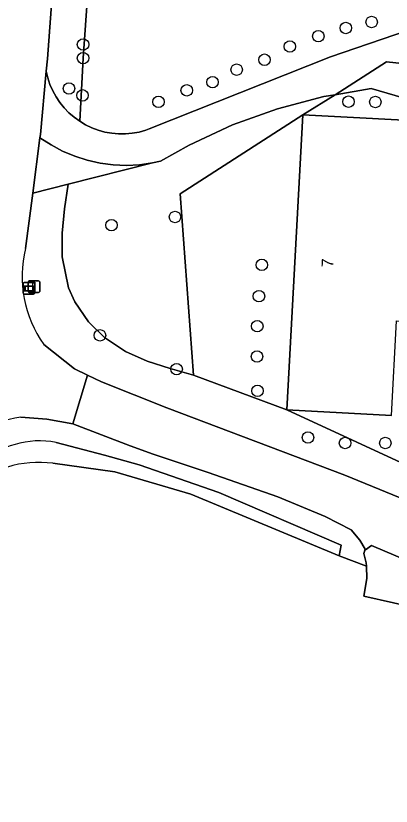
# Model space of a CAD drawing. Extents: x 163859 to 164644, y 379566 to 382155.
# Drawn here: x 164438.1 to 164470.1, y 381270.8 to 381338.2 of the extents above; entities that cross this region are included whole.
import ezdxf

# ---------------------------------------------------------------- set-up
doc = ezdxf.new("R2010")
doc.units = 0
for name, color, linetype in [('IMGEO_Boom', 7, 'Continuous'), ('IMGEO_Erf', 7, 'Continuous'), ('IMGEO_Grasland_overig', 7, 'Continuous'), ('IMGEO_Groenvoorziening', 7, 'Continuous'), ('IMGEO_Lichtmast', 7, 'Continuous'), ('IMGEO_Pand', 7, 'Continuous'), ('IMGEO_Pand_nummerreeks', 7, 'Continuous'), ('IMGEO_Rijbaan_lokaal_gesloten', 7, 'Continuous'), ('IMGEO_Rijbaan_lokaal_onverhard', 7, 'Continuous'), ('IMGEO_Rijbaan_lokaal_open', 7, 'Continuous'), ('IMGEO_Waterloop', 7, 'Continuous'), ('IMGEO_Wegwijzer', 7, 'Continuous')]:
    doc.layers.add(name, color=color, linetype=linetype)

msp = doc.modelspace()

# ---------------------------------------------------------------- linework, layer by layer
at = {"layer": 'IMGEO_Boom'}
for centre in [(164466.181, 381337.123), (164468.388, 381337.632), (164463.846, 381336.431), (164443.791, 381335.711), (164461.422, 381335.541), (164443.791, 381334.557), (164459.253, 381334.417), (164456.883, 381333.568), (164454.831, 381332.506), (164442.59, 381331.967), (164452.627, 381331.808), (164443.738, 381331.377), (164450.222, 381330.825), (164466.417, 381330.842), (164468.704, 381330.815), (164451.629, 381321.013), (164446.217, 381320.312), (164459.029, 381316.926), (164458.783, 381314.264), (164458.64, 381311.705), (164445.23, 381310.921), (164458.619, 381309.125), (164451.764, 381308.047), (164458.66, 381306.197), (164462.962, 381302.22), (164466.124, 381301.745), (164469.554, 381301.745)]:
    msp.add_circle(centre, 0.489, dxfattribs=at)
at = {"layer": 'IMGEO_Erf'}
for points in [[(164476.058, 381329.711), (164468.34, 381331.955), (164465.276, 381331.438), (164462.527, 381329.731), (164474.919, 381329.061)], [(164470.072, 381304.084), (164461.167, 381304.566), (164478.695, 381296.475)], [(164540.482, 381264.151), (164540.217, 381265.042), (164529.128, 381268.212), (164519.659, 381272.559), (164519.129, 381272.749), (164519.009, 381272.239), (164518.443, 381269.846), (164506.288, 381272.625), (164507.244, 381276.67), (164507.32, 381276.993), (164482.611, 381286.224), (164473.391, 381289.208), (164473.355, 381289.222), (164473.052, 381288.89), (164472.767, 381287.543), (164467.729, 381288.691), (164467.974, 381290.201), (164467.944, 381291.26), (164465.612, 381292.138), (164452.976, 381297.383), (164446.503, 381299.301), (164441.209, 381300.014)]]:
    msp.add_lwpolyline(points, dxfattribs=at)
msp.add_lwpolyline([(164462.527, 381329.731), (164452.067, 381322.978), (164453.209, 381307.534), (164461.167, 381304.566)], close=True, dxfattribs=at)
msp.add_arc((164439.999, 381291.545), 8.555, 81.86677, 108.05094, dxfattribs=at)
at = {"layer": 'IMGEO_Grasland_overig'}
msp.add_lwpolyline([(164468.34, 381331.955), (164476.058, 381329.711), (164478.189, 381332.234), (164478.125, 381332.347), (164478.018, 381332.569), (164477.931, 381332.8), (164477.865, 381333.037), (164477.821, 381333.279), (164477.814, 381333.353), (164469.657, 381334.244), (164465.276, 381331.438)], close=True, dxfattribs=at)
at = {"layer": 'IMGEO_Groenvoorziening'}
for points in [[(164444.131, 381379.084), (164441.337, 381342.212), (164440.752, 381334.49), (164440.655, 381333.446), (164440.788, 381332.875), (164440.972, 381332.318), (164441.205, 381331.779), (164441.485, 381331.264), (164441.811, 381330.775), (164442.178, 381330.318), (164442.585, 381329.895), (164443.028, 381329.51), (164443.503, 381329.167), (164443.791, 381334.557), (164444.186, 381340.215), (164444.308, 381342.237), (164444.374, 381343.319), (164446.95, 381371.56), (164448.25, 381394.833), (164448.452, 381420.113), (164447.939, 381444.466), (164447.883, 381447.149), (164448.535, 381452.5)], [(164511.933, 381342.807), (164510.514, 381342.795), (164444.308, 381342.237), (164444.186, 381340.215), (164443.791, 381334.557), (164443.503, 381329.167), (164444.007, 381328.867), (164444.537, 381328.613), (164445.086, 381328.408), (164445.652, 381328.253), (164446.229, 381328.149), (164446.814, 381328.097), (164447.4, 381328.097), (164447.985, 381328.149), (164448.562, 381328.254), (164449.128, 381328.41), (164449.427, 381328.515), (164464.882, 381334.661)], [(164464.882, 381334.661), (164471.455, 381336.919), (164479.318, 381338.909), (164487.327, 381340.189), (164500, 381340.973), (164507.731, 381341.451), (164508.254, 381341.435), (164508.776, 381341.467), (164509.294, 381341.544), (164509.802, 381341.668), (164510.298, 381341.836), (164510.588, 381341.959)], [(164478.695, 381296.475), (164461.167, 381304.566), (164453.209, 381307.534), (164451.204, 381308.088), (164449.251, 381308.732), (164447.405, 381309.557), (164445.606, 381310.742), (164444.249, 381312.082), (164443.088, 381313.781), (164442.544, 381314.984), (164442.002, 381317.607), (164441.998, 381319.634), (164442.21, 381321.705), (164442.531, 381323.8), (164439.498, 381323.039), (164438.88, 381318.314)], [(164440.438, 381310.155), (164443.049, 381308.08), (164444.17, 381307.541), (164445.359, 381306.969), (164450.929, 381304.74), (164466.11, 381299.002), (164477.26, 381294.425), (164486.159, 381290.941), (164495.223, 381288.05), (164508.891, 381283.704), (164521.819, 381279.707), (164528.232, 381278.11), (164532.041, 381277.331)], [(164441.495, 381301.788), (164445.628, 381300.717), (164448.566, 381299.888), (164455.369, 381297.524), (164465.778, 381293.037), (164465.612, 381292.138), (164467.944, 381291.26), (164467.936, 381291.524), (164467.716, 381292.319), (164467.841, 381292.683), (164467.37, 381293.461), (164466.649, 381294.342), (164464.441, 381295.494), (164460.4, 381297.168), (164454.459, 381299.235), (164449.776, 381300.806), (164447.793, 381301.508), (164442.93, 381303.374), (164440.691, 381303.766), (164438.496, 381303.942)]]:
    msp.add_lwpolyline(points, dxfattribs=at)
for points in [[(164452.067, 381322.978), (164462.527, 381329.731), (164465.276, 381331.438), (164464.32, 381331.277), (164460.376, 381330.243), (164456.541, 381328.86), (164452.845, 381327.14), (164450.405, 381325.773), (164449.715, 381325.625), (164442.531, 381323.8), (164442.21, 381321.705), (164441.998, 381319.634), (164442.002, 381317.607), (164442.544, 381314.984), (164443.088, 381313.781), (164444.249, 381312.082), (164445.606, 381310.742), (164447.405, 381309.557), (164449.251, 381308.732), (164451.204, 381308.088), (164453.209, 381307.534)], [(164449.715, 381325.625), (164448.604, 381325.47), (164447.483, 381325.415), (164446.361, 381325.461), (164445.248, 381325.606), (164444.153, 381325.85), (164443.084, 381326.191), (164442.049, 381326.627), (164441.058, 381327.153), (164440.117, 381327.765), (164439.498, 381323.039), (164442.531, 381323.8)]]:
    msp.add_lwpolyline(points, close=True, dxfattribs=at)
for centre, radius, start, end in [((164448.537, 381315.93), 9.947, 166.13246, 215.48905), ((164439.55, 381295.205), 8.801, 96.87712, 149.56303), ((164440.073, 381294.503), 7.422, 78.955, 133.64674)]:
    msp.add_arc(centre, radius, start, end, dxfattribs=at)
at = {"layer": 'IMGEO_Lichtmast'}
for p, q in [((164439.102, 381314.671), (164439.102, 381315.471)), ((164439.102, 381315.471), (164439.102, 381314.671)), ((164439.202, 381315.571), (164439.992, 381315.571)), ((164439.992, 381315.571), (164439.202, 381315.571)), ((164440.092, 381315.471), (164440.092, 381314.671)), ((164440.092, 381314.671), (164440.092, 381315.471)), ((164439.992, 381314.571), (164439.202, 381314.571)), ((164439.202, 381314.571), (164439.992, 381314.571))]:
    msp.add_line(p, q, dxfattribs=at)
msp.add_lwpolyline([(164439.522, 381315.446), (164439.672, 381315.446), (164439.672, 381314.696), (164439.522, 381314.696), (164439.522, 381315.446)], dxfattribs=at)
for centre, start, end in [((164439.202, 381315.471), 90, 180), ((164439.202, 381315.471), 90, 180), ((164439.992, 381315.471), 0, 90), ((164439.992, 381315.471), 360, 90), ((164439.202, 381314.671), 180, 270), ((164439.202, 381314.671), 180, 270), ((164439.992, 381314.671), 270, 0), ((164439.992, 381314.671), 270, 0)]:
    msp.add_arc(centre, 0.1, start, end, dxfattribs=at)
at = {"layer": 'IMGEO_Pand'}
msp.add_lwpolyline([(164462.527, 381329.731), (164461.167, 381304.566), (164470.072, 381304.084), (164470.509, 381312.16), (164473.995, 381311.972), (164474.919, 381329.061)], close=True, dxfattribs=at)
at = {"layer": 'IMGEO_Rijbaan_lokaal_gesloten'}
for points in [[(164438.88, 381318.314), (164439.498, 381323.039), (164440.117, 381327.765), (164440.155, 381328.055), (164440.655, 381333.446), (164440.752, 381334.49), (164441.337, 381342.212), (164444.131, 381379.084)], [(164438.496, 381303.942), (164440.691, 381303.766), (164442.93, 381303.374), (164444.17, 381307.541), (164443.049, 381308.08), (164440.438, 381310.155)]]:
    msp.add_lwpolyline(points, dxfattribs=at)
for centre, radius, start, end in [((164448.537, 381315.93), 9.947, 166.13246, 215.48905), ((164439.55, 381295.205), 8.801, 96.87712, 149.56303)]:
    msp.add_arc(centre, radius, start, end, dxfattribs=at)
at = {"layer": 'IMGEO_Rijbaan_lokaal_onverhard'}
for points in [[(164471.455, 381336.919), (164464.882, 381334.661), (164449.427, 381328.515), (164449.128, 381328.41), (164448.562, 381328.254), (164447.985, 381328.149), (164447.4, 381328.097), (164446.814, 381328.097), (164446.229, 381328.149), (164445.652, 381328.253), (164445.086, 381328.408), (164444.537, 381328.613), (164444.007, 381328.867), (164443.503, 381329.167), (164443.028, 381329.51), (164442.585, 381329.895), (164442.178, 381330.318), (164441.811, 381330.775), (164441.485, 381331.264), (164441.205, 381331.779), (164440.972, 381332.318), (164440.788, 381332.875), (164440.655, 381333.446), (164440.155, 381328.055), (164440.117, 381327.765), (164441.058, 381327.153), (164442.049, 381326.627), (164443.084, 381326.191), (164444.153, 381325.85), (164445.248, 381325.606), (164446.361, 381325.461), (164447.483, 381325.415), (164448.604, 381325.47), (164449.715, 381325.625), (164450.405, 381325.773), (164452.845, 381327.14), (164456.541, 381328.86), (164460.376, 381330.243), (164464.32, 381331.277), (164465.276, 381331.438), (164469.657, 381334.244), (164477.814, 381333.353)], [(164477.26, 381294.425), (164466.11, 381299.002), (164450.929, 381304.74), (164445.359, 381306.969), (164444.17, 381307.541), (164442.93, 381303.374), (164447.793, 381301.508), (164449.776, 381300.806), (164454.459, 381299.235), (164460.4, 381297.168), (164464.441, 381295.494), (164466.649, 381294.342), (164467.37, 381293.461), (164467.841, 381292.683), (164467.86, 381292.651), (164468.367, 381293.007), (164474.215, 381290.55)]]:
    msp.add_lwpolyline(points, dxfattribs=at)
at = {"layer": 'IMGEO_Rijbaan_lokaal_open'}
msp.add_lwpolyline([(164474.215, 381290.55), (164468.367, 381293.007), (164467.86, 381292.651), (164467.841, 381292.683), (164467.716, 381292.319), (164467.936, 381291.524), (164467.944, 381291.26), (164467.974, 381290.201), (164467.729, 381288.691), (164472.767, 381287.543), (164473.052, 381288.89), (164473.355, 381289.222), (164474.18, 381290.126)], close=True, dxfattribs=at)
at = {"layer": 'IMGEO_Waterloop'}
for points in [[(164445.628, 381300.717), (164441.495, 381301.788)], [(164441.209, 381300.014), (164446.503, 381299.301), (164452.976, 381297.383), (164465.612, 381292.138), (164465.778, 381293.037), (164455.369, 381297.524), (164448.566, 381299.888), (164445.628, 381300.717)]]:
    msp.add_lwpolyline(points, dxfattribs=at)
for centre, radius, start, end in [((164440.073, 381294.503), 7.422, 78.955, 133.64674), ((164439.999, 381291.545), 8.555, 81.86677, 108.05094)]:
    msp.add_arc(centre, radius, start, end, dxfattribs=at)
at = {"layer": 'IMGEO_Wegwijzer'}
for p, q in [((164438.676, 381314.522), (164438.676, 381315.322)), ((164438.676, 381315.322), (164438.676, 381314.522)), ((164438.776, 381315.422), (164439.566, 381315.422)), ((164439.566, 381315.422), (164438.776, 381315.422)), ((164439.666, 381315.322), (164439.666, 381314.522)), ((164439.666, 381314.522), (164439.666, 381315.322)), ((164439.566, 381314.422), (164438.776, 381314.422)), ((164438.776, 381314.422), (164439.566, 381314.422))]:
    msp.add_line(p, q, dxfattribs=at)
for points in [[(164438.777, 381315.154), (164439.565, 381315.154), (164439.565, 381314.69), (164438.777, 381314.69), (164438.777, 381315.154)], [(164438.842, 381315.089), (164438.842, 381314.755), (164439.5, 381314.755), (164439.5, 381315.089), (164438.842, 381315.089)]]:
    msp.add_lwpolyline(points, dxfattribs=at)
for centre, start, end in [((164438.776, 381315.322), 90, 180), ((164438.776, 381315.322), 90, 180), ((164439.566, 381315.322), 0, 90), ((164439.566, 381315.322), 360, 90), ((164438.776, 381314.522), 180, 270), ((164438.776, 381314.522), 180, 270), ((164439.566, 381314.522), 270, 0), ((164439.566, 381314.522), 270, 0)]:
    msp.add_arc(centre, 0.1, start, end, dxfattribs=at)

# ---------------------------------------------------------------- texts
at = {"layer": 'IMGEO_Pand_nummerreeks'}
msp.add_text('7', height=1, rotation=86.90656, dxfattribs=at).set_placement((164465.108, 381316.697))

doc.saveas('drawing.dxf')
